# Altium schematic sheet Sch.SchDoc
size A4
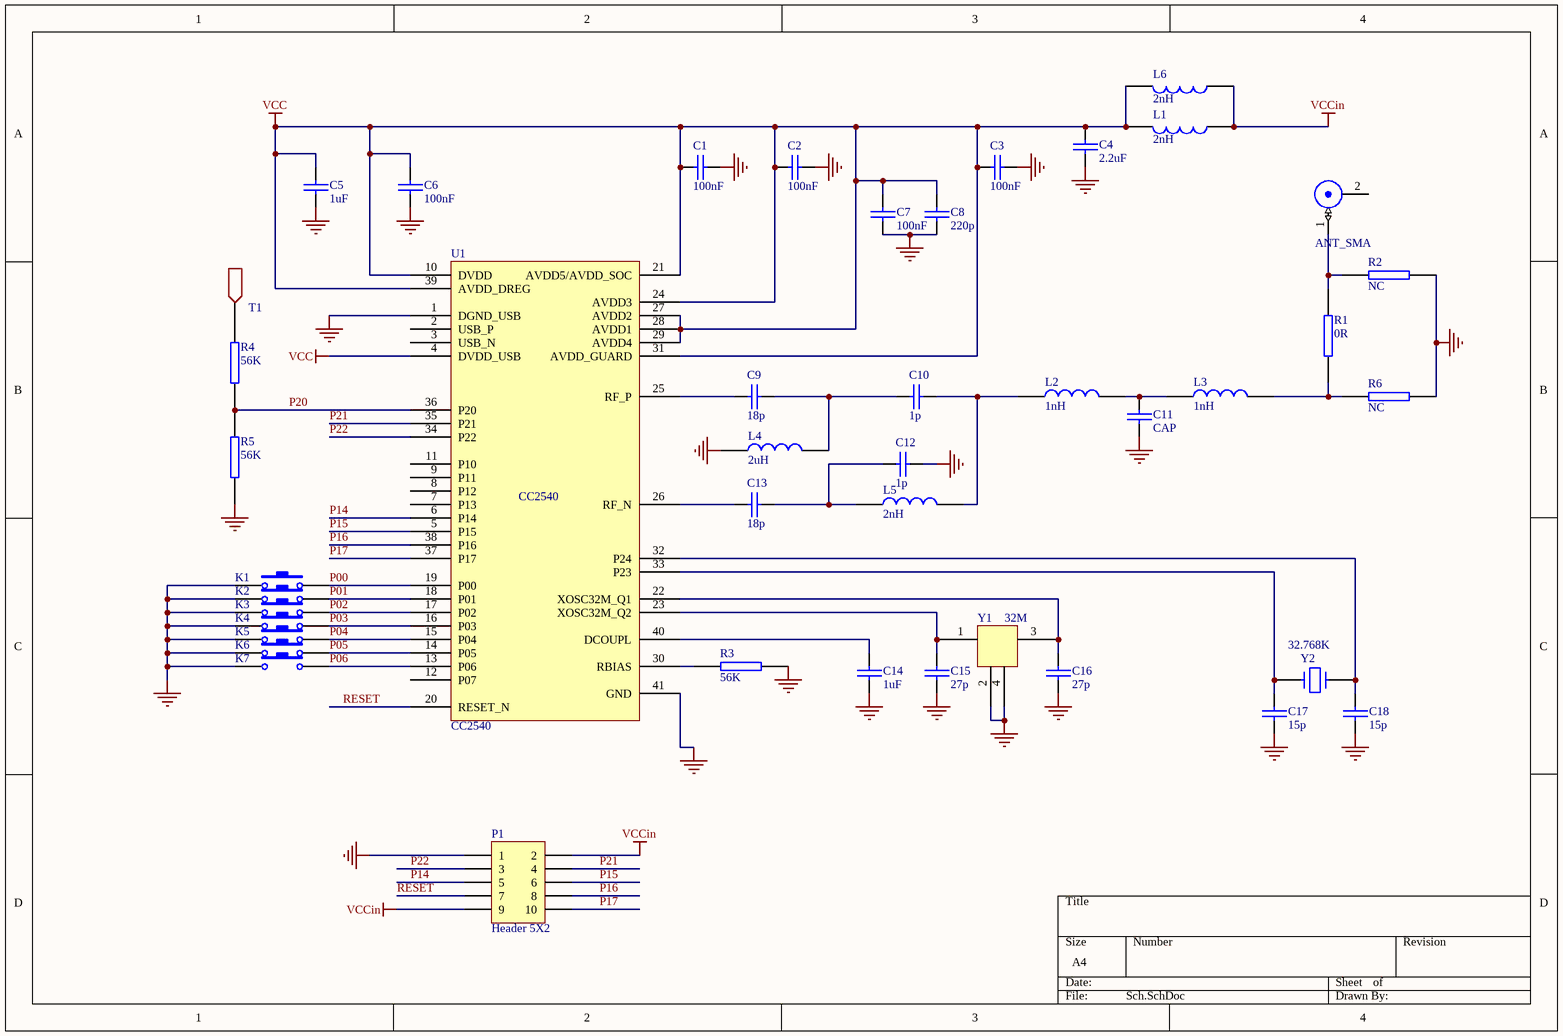
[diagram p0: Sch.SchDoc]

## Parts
?  ANT_SMA  [Wire]
C1  100nF  [0402_SMALL]
C2  100nF  [0402_SMALL]
C3  100nF  [0402_SMALL]
C4  2.2uF  [0402_SMALL]
C5  1uF  [0402_SMALL]
C6  100nF  [0402_SMALL]
C7  100nF  [0402_SMALL]
C8  220p  [0402_SMALL]
C9  18p  [0402_SMALL]
C10  1p  [0402_SMALL]
C11  CAP  [0402_SMALL]
C12  1p  [0402_SMALL]
C13  18p  [0402_SMALL]
C14  1uF  [0402_SMALL]
C15  27p  [0402_SMALL]
C16  27p  [0402_SMALL]
C17  15p  [0402_SMALL]
C18  15p  [0402_SMALL]
K1  (no value)  [MiniKey]
K2  (no value)  [MiniKey]
K3  (no value)  [MiniKey]
K4  (no value)  [MiniKey]
K5  (no value)  [MiniKey]
K6  (no value)  [MiniKey]
K7  (no value)  [MiniKey]
L1  2nH  [0402_SMALL]
L2  1nH  [0402_SMALL]
L3  1nH  [0402_SMALL]
L4  2uH  [0402_SMALL]
L5  2nH  [0402_SMALL]
L6  2nH  [0402_SMALL]
P1  Header 5X2  [HDR2_5]
R1  0R  [0402_SMALL]
R2  NC  [0402_SMALL]
R3  56K  [0402_SMALL]
R4  56K  [0402_SMALL]
R5  56K  [0402_SMALL]
R6  NC  [0402_SMALL]
T1  Pad  [T]  (value not drawn)
U1  CC2540  [CC2530_QFN]
Y1  32M  [CY_3225]
Y2  32.768K  [CRYSTAL_3215]

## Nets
GND: C1.2 C2.2 C3.2 C4.2 C5.2 C6.2 C7.1 C8.1 C11.2 C12.2 C14.2 C15.2 C16.2 C17.2 C18.2 K1.1 K2.1 K3.1 K4.1 K5.1 K6.1 K7.1 L4.1 P1.1 R2.1 R3.2 R5.1 R6.1 U1.1(DGND_USB) U1.41(GND) Y1.2 Y1.4
VCC: C1.1 C2.1 C3.1 C4.1 C5.1 C6.1 C7.2 C8.2 L1.2 L6.2 U1.4(DVDD_USB) U1.10(DVDD) U1.21(AVDD5/AVDD_SOC) U1.24(AVDD3) U1.27(AVDD2) U1.28(AVDD1) U1.29(AVDD4) U1.31(AVDD_GUARD) U1.39(AVDD_DREG)
VCCin: L1.1 L6.1 P1.2 P1.9
P00: K1.2 U1.19(P00)
P01: K2.2 U1.18(P01)
P02: K3.2 U1.17(P02)
P03: K4.2 U1.16(P03)
P04: K5.2 U1.15(P04)
P05: K6.2 U1.14(P05)
P06: K7.2 U1.13(P06)
P14: P1.5 U1.6(P14)
P15: P1.6 U1.5(P15)
P16: P1.8 U1.38(P16)
P17: P1.10 U1.37(P17)
P20: R4.1 R5.2 U1.36(P20)
P21: P1.4 U1.35(P21)
P22: P1.3 U1.34(P22)
RESET: P1.7 U1.20(RESET_N)
Net?_1: ?.1 R1.2 R2.2
NetC9_1: C9.1 U1.25(RF_P)
NetC9_2: C9.2 C10.1 L4.2
NetC10_2: C10.2 L2.1 L5.2
NetC11_1: C11.1 L2.2 L3.1
NetC12_1: C12.1 C13.2 L5.1
NetC13_1: C13.1 U1.26(RF_N)
NetC14_1: C14.1 U1.40(DCOUPL)
NetC15_1: C15.1 U1.23(XOSC32M_Q2) Y1.1
NetC16_1: C16.1 U1.22(XOSC32M_Q1) Y1.3
NetC17_1: C17.1 U1.33(P23) Y2.1
NetC18_1: C18.1 U1.32(P24) Y2.2
NetL3_2: L3.2 R1.1 R6.2
NetR3_1: R3.1 U1.30(RBIAS)
NetR4_2: R4.2 T1.1

Not connected (* = marked no-connect by the designer): ? 2; U1 2(USB_P) 3(USB_N) 7(P13) 8(P12) 9(P11) 11(P10) 12(P07)

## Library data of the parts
C1-C18 = CAP: Capacitor
K1-K7 = SW-PB: Switch
L1-L6 = INDUCTOR
P1 = Header 5X2: Header, 5-Pin, Dual row
R1-R6 = RES2
Y1 = CY_3225
Y2 = CRYSTAL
